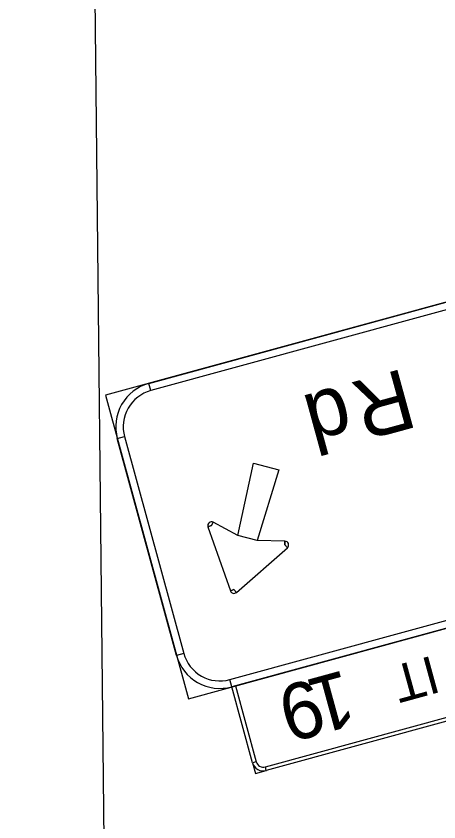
# Model space of a CAD drawing. Extents: x 2001876 to 2025694, y 804561 to 868938.
# Drawn here: x 2010635.1 to 2010778, y 826553.5 to 826826.1 of the extents above; entities that cross this region are included whole.
import ezdxf

# ---------------------------------------------------------------- set-up
doc = ezdxf.new("R2010")
doc.units = 0
doc.layers.add('RD_SHT_ShtClip', color=7, linetype='Continuous')
doc.layers.add('TR SN EXTRUDED PANEL SIGNS- MOUNTED OVERHEAD', color=7, linetype='Continuous')

msp = doc.modelspace()

# ---------------------------------------------------------------- linework, layer by layer
at = {"layer": 'RD_SHT_ShtClip'}
msp.add_line((2010698.28, 823374.8), (2010635.06, 829374.39), dxfattribs=at)
at = {"layer": 'TR SN EXTRUDED PANEL SIGNS- MOUNTED OVERHEAD'}
for p, q in [((2010680.6, 826699.38), (2010679.93, 826701.82)), ((2010669.28, 826683.15), (2010671.72, 826683.82)), ((2010701.14, 826653.72), (2010701.74, 826654.84)), ((2010699.94, 826653.3), (2010701.14, 826653.72)), ((2010725.98, 826648.47), (2010725.95, 826647.2)), ((2010725.95, 826647.2), (2010726.78, 826646.25)), ((2010708.72, 826632.08), (2010707.52, 826631.67)), ((2010709.55, 826631.13), (2010708.72, 826632.08)), ((2010691.76, 826610.51), (2010689.32, 826609.84)), ((2010707.99, 826599.19), (2010707.32, 826601.63)), ((2010716.23, 826573.86), (2010715, 826573.53)), ((2010719.67, 826570.86), (2010719.34, 826572.08))]:
    msp.add_line(p, q, dxfattribs=at)
for points in [[(2010907.2, 826763.94), (2010665.27, 826697.81), (2010693.33, 826595.18), (2010935.25, 826661.31), (2010907.2, 826763.94)], [(2010893.2, 826757.49), (2010680.6, 826699.38), (2010679.93, 826701.82), (2010892.53, 826759.94), (2010893.2, 826757.49)], [(2010671.72, 826683.82), (2010691.76, 826610.51), (2010689.32, 826609.84), (2010669.28, 826683.15), (2010671.72, 826683.82)], [(2010715.37, 826674.87), (2010723.94, 826672.61), (2010716.59, 826648.68), (2010710.01, 826650.41), (2010715.37, 826674.87)], [(2010707.32, 826601.63), (2010919.92, 826659.74), (2010920.59, 826657.3), (2010707.99, 826599.19), (2010707.32, 826601.63)], [(2010708.72, 826632.08), (2010709.55, 826631.13), (2010726.78, 826646.25), (2010725.95, 826647.2), (2010725.98, 826648.47), (2010716.59, 826648.68), (2010710.01, 826650.41), (2010701.74, 826654.84), (2010701.14, 826653.72), (2010699.94, 826653.3), (2010707.52, 826631.67), (2010708.72, 826632.08)], [(2010709.21, 826599.52), (2010716.23, 826573.86), (2010715, 826573.53), (2010707.99, 826599.19), (2010709.21, 826599.52)], [(2010719.34, 826572.08), (2010814.64, 826598.14), (2010814.97, 826596.91), (2010719.67, 826570.86), (2010719.34, 826572.08)]]:
    msp.add_lwpolyline(points, close=True, dxfattribs=at)
msp.add_lwpolyline([(2010715, 826573.53), (2010716.01, 826569.86), (2010719.67, 826570.86)], dxfattribs=at)
for centre, radius, start, end in [((2010683.94, 826687.16), 15.2, 105.2889, 195.2891), ((2010683.94, 826687.16), 12.67, 105.2889, 195.2891), ((2010701.14, 826653.72), 1.27, 61.8426, 199.3084), ((2010725.95, 826647.2), 1.27, 311.2692, 88.735), ((2010708.72, 826632.08), 1.27, 199.3081, 311.2692), ((2010703.98, 826613.85), 12.67, 195.2888, 285.289), ((2010703.98, 826613.85), 15.2, 195.2888, 285.289), ((2010718.67, 826574.53), 3.8, 195.2888, 285.289), ((2010718.67, 826574.53), 2.53, 195.2888, 285.289)]:
    msp.add_arc(centre, radius, start, end, dxfattribs=at)

# ---------------------------------------------------------------- texts
for s, height, p in [('R', 20.27, (2010766.14, 826707)), ('d', 20.27, (2010745.5, 826701.36)), ('I', 12.67, (2010775.87, 826609.86)), ('T', 12.67, (2010771.25, 826608.6)), ('1', 19, (2010746.17, 826605.03)), ('9', 19, (2010736.01, 826602.25))]:
    msp.add_text(s, height=height, rotation=195.2888, dxfattribs=at).set_placement(p)

doc.saveas('drawing.dxf')
